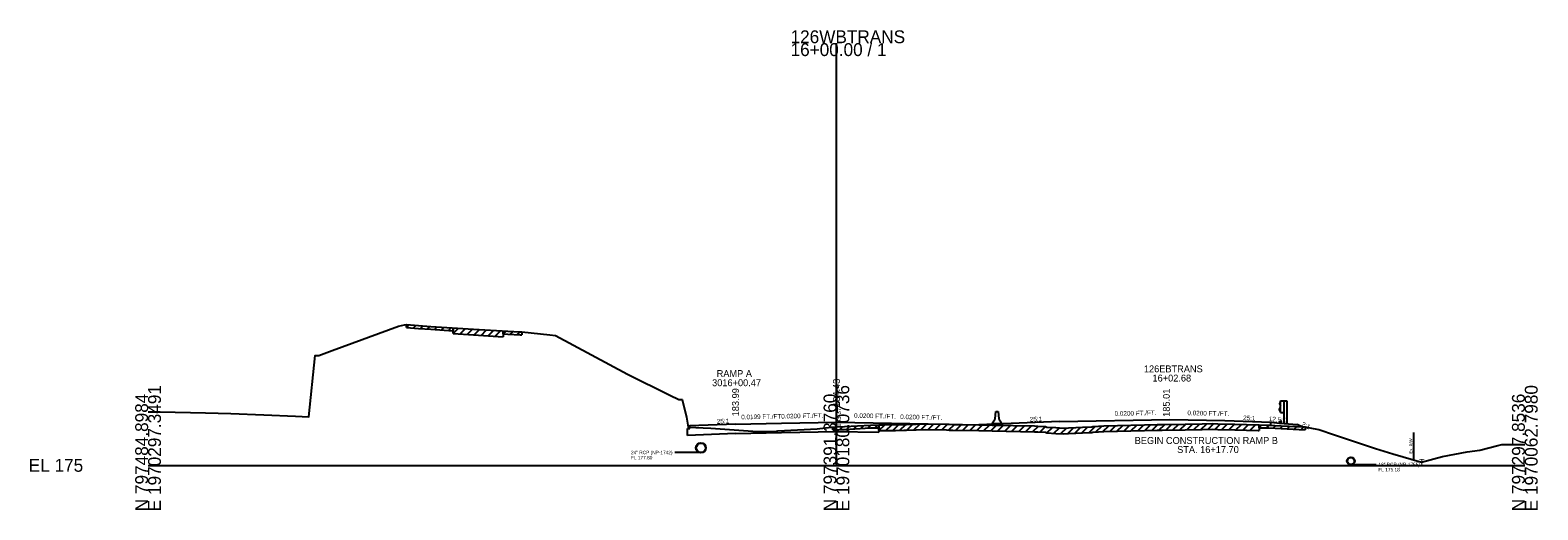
# Model space of a CAD drawing. Extents: x -6494 to 1970605, y -10 to 798140.
# Drawn here: x -25.7 to 302.8, y 8490.3 to 8594.8 of the extents above; entities that cross this region are included whole.
import ezdxf

# ---------------------------------------------------------------- set-up
doc = ezdxf.new("R2010")
doc.units = 0
for name, color, linetype in [('Default', 7, 'Continuous'), ('RD_GPK_XS_Cell', 7, 'Continuous'), ('RD_Sketch1', 7, 'Continuous'), ('RD_XS_Base', 7, 'Continuous'), ('RD_XS_CurbTop', 7, 'Continuous'), ('RD_XS_EarthShd', 7, 'Continuous'), ('RD_XS_ExGround', 7, 'Continuous'), ('RD_XS_ExPaveRet', 7, 'Continuous'), ('RD_XS_ExRW', 7, 'Continuous'), ('RD_XS_GR', 7, 'Continuous'), ('RD_XS_Misc_Line', 7, 'Continuous'), ('RD_XS_Pave', 7, 'Continuous'), ('RD_XS_PaveOvlay', 7, 'Continuous'), ('RD_XS_PaveShd', 7, 'Continuous'), ('RD_XS_Pipe', 7, 'Continuous'), ('RD_XS_TieSlope', 7, 'Continuous'), ('RD_XS_TX_Elev_EX', 7, 'Continuous'), ('RD_XS_TX_Elev_PR', 7, 'Continuous'), ('RD_XS_TX_Notes', 7, 'Continuous'), ('RD_XS_TX_Profile', 7, 'Continuous'), ('RD_XS_TX_ShdSlope', 7, 'Continuous'), ('RD_XS_TX_Slope', 7, 'Continuous'), ('RD_XS_TX_Station', 7, 'Continuous')]:
    doc.layers.add(name, color=color, linetype=linetype)

msp = doc.modelspace()

# ---------------------------------------------------------------- linework, layer by layer
at = {"layer": 'Default'}
for p, q in [((184, 8509.28), (184.58, 8510.11)), ((184, 8509.03), (184, 8509.28)), ((186, 8509.03), (184, 8509.03)), ((184.58, 8510.11), (184.75, 8511.7)), ((184.75, 8511.7), (185.25, 8511.7)), ((185.25, 8511.7), (185.42, 8510.11)), ((185.42, 8510.11), (186, 8509.28)), ((186, 8509.28), (186, 8509.03))]:
    msp.add_line(p, q, dxfattribs=at)
at = {"layer": 'RD_GPK_XS_Cell'}
for p, q in [((150, 8500), (150, 8591.95)), ((0, 8500), (150, 8500)), ((150, 8500), (300, 8500))]:
    msp.add_line(p, q, dxfattribs=at)
at = {"layer": 'RD_XS_Base'}
for p, q in [((244.65, 8508.75), (244.65, 8509.37)), ((117.52, 8508.01), (118.02, 8508.03)), ((117.52, 8506.53), (117.52, 8508.01)), ((128.02, 8506.95), (117.52, 8506.53)), ((118.02, 8508.03), (118.02, 8508.59)), ((128.02, 8506.95), (138, 8507.15)), ((138, 8507.15), (150, 8507.39)), ((150, 8507.39), (159.22, 8507.21))]:
    msp.add_line(p, q, dxfattribs=at)
at = {"layer": 'RD_XS_CurbTop'}
for p, q in [((246.52, 8509.22), (246.77, 8509.67)), ((246.52, 8509.22), (246.99, 8509.18)), ((246.99, 8509.18), (246.93, 8509.62))]:
    msp.add_line(p, q, dxfattribs=at)
msp.add_ellipse((246.84, 8509.59), major_axis=(0, -0.131), ratio=0.686, start_param=1.762783, end_param=4.036677, dxfattribs=at)
at = {"layer": 'RD_XS_EarthShd'}
for p, q in [((244.65, 8509.37), (246.65, 8509.21)), ((118.02, 8508.59), (117.66, 8508.56))]:
    msp.add_line(p, q, dxfattribs=at)
at = {"layer": 'RD_XS_ExGround'}
msp.add_lwpolyline([(0, 8511.65), (2.64, 8511.67), (12.5, 8511.42), (15.24, 8511.38), (18.05, 8511.29), (25.21, 8510.99), (32.13, 8510.72), (35.03, 8510.6), (36.4, 8523.91), (37.18, 8523.94), (40.12, 8525.01), (54.59, 8530.32), (55.9, 8530.57), (56.28, 8530.65), (58.91, 8530.47), (61.63, 8530.26), (70.93, 8529.67), (78.36, 8529.19), (81.05, 8529.09), (81.44, 8529.07), (87.58, 8528.43), (88.8, 8528.3), (104.46, 8519.89), (113.72, 8515.27), (115.64, 8514.32), (116.4, 8514.31), (117.3, 8510.52), (117.7, 8508.34), (122.61, 8508.08), (132.82, 8507.36), (136.91, 8507.46), (137.21, 8507.48), (145.83, 8507.96), (148.86, 8508.29), (149.22, 8508.33), (150, 8508.37), (151.75, 8508.47), (157.44, 8508.77), (162.85, 8508.87), (164.65, 8508.9), (165.29, 8508.91), (169.5, 8509.02), (173.96, 8508.95), (174.6, 8508.94), (175.39, 8508.93), (181, 8508.83), (183.95, 8508.77), (193.13, 8508.58), (193.91, 8508.54), (195.53, 8508.45), (195.82, 8508.32), (197.84, 8508.21), (199.49, 8508.11), (200.58, 8508.18), (202.17, 8508.25), (203.6, 8508.32), (205.65, 8508.38), (205.9, 8508.49), (207.14, 8508.56), (208.3, 8508.61), (217.14, 8508.82), (219.89, 8508.89), (221.01, 8508.91), (225.96, 8508.99), (229.69, 8509.06), (231.99, 8509.1), (233.09, 8509.07), (236.82, 8508.96), (241.9, 8508.83), (244.2, 8508.77), (246.88, 8508.64), (252.11, 8508.36), (253.88, 8508.05), (255.13, 8507.82), (258.54, 8506.64), (267.43, 8503.69), (271.21, 8502.53), (277.51, 8500.66), (282.05, 8501.91), (287.41, 8502.92), (290.22, 8503.32), (294.11, 8504.35), (295.01, 8504.57), (300, 8504.57)], dxfattribs=at)
at = {"layer": 'RD_XS_ExPaveRet'}
for p, q in [((56.28, 8530.02), (56.28, 8530.65)), ((56.28, 8530.02), (58.91, 8529.84)), ((58.91, 8529.84), (61.63, 8529.64)), ((61.63, 8529.64), (66.45, 8529.33)), ((66.45, 8528.7), (66.45, 8529.95)), ((66.45, 8529.95), (66.45, 8529.33)), ((77.4, 8529.25), (77.4, 8528)), ((77.4, 8528.63), (77.4, 8529.25)), ((81.44, 8529.07), (81.44, 8528.44)), ((66.45, 8528.7), (70.93, 8528.42)), ((70.93, 8528.42), (77.4, 8528)), ((77.4, 8528.63), (78.36, 8528.57)), ((78.36, 8528.57), (81.05, 8528.46)), ((81.05, 8528.46), (81.44, 8528.44)), ((149.22, 8507.71), (149.22, 8508.33)), ((149.22, 8507.71), (150, 8507.75)), ((150, 8507.75), (151.75, 8507.84)), ((151.75, 8507.84), (157.44, 8508.15)), ((157.44, 8508.15), (159.22, 8508.18)), ((159.22, 8507.56), (159.22, 8508.81)), ((159.22, 8508.81), (159.22, 8508.18)), ((159.22, 8507.56), (162.85, 8507.62)), ((162.85, 8507.62), (164.65, 8507.65)), ((164.65, 8507.65), (165.29, 8507.66)), ((165.29, 8507.66), (169.5, 8507.77)), ((169.5, 8507.77), (173.96, 8507.7)), ((173.96, 8507.7), (174.6, 8507.69)), ((174.6, 8507.69), (175.39, 8507.68)), ((175.39, 8507.68), (181, 8507.58)), ((181, 8507.58), (183.95, 8507.52)), ((183.95, 8507.52), (193.13, 8507.33)), ((193.13, 8507.33), (193.91, 8507.29)), ((193.91, 8507.29), (195.53, 8507.2)), ((195.53, 8507.2), (195.82, 8507.07)), ((195.82, 8507.07), (197.84, 8506.96)), ((197.84, 8506.96), (199.49, 8506.86)), ((199.49, 8506.86), (200.58, 8506.93)), ((200.58, 8506.93), (202.17, 8507)), ((202.17, 8507), (203.6, 8507.07)), ((203.6, 8507.07), (205.65, 8507.13)), ((205.65, 8507.13), (205.9, 8507.24)), ((205.9, 8507.24), (207.14, 8507.31)), ((207.14, 8507.31), (208.3, 8507.36)), ((208.3, 8507.36), (217.14, 8507.57)), ((217.14, 8507.57), (219.89, 8507.64)), ((219.89, 8507.64), (221.01, 8507.66)), ((221.01, 8507.66), (225.96, 8507.74)), ((225.96, 8507.74), (229.69, 8507.81)), ((229.69, 8507.81), (231.99, 8507.85)), ((231.99, 8507.85), (233.09, 8507.82)), ((233.09, 8507.82), (236.82, 8507.71)), ((236.82, 8507.71), (241.9, 8507.58)), ((241.9, 8507.58), (242.11, 8507.57)), ((242.11, 8508.82), (242.11, 8507.57)), ((242.11, 8508.2), (242.11, 8508.82)), ((242.11, 8508.2), (244.2, 8508.15)), ((244.2, 8508.15), (246.88, 8508.01)), ((246.88, 8508.01), (252.11, 8507.74)), ((252.11, 8508.36), (252.11, 8507.74))]:
    msp.add_line(p, q, dxfattribs=at)
at = {"layer": 'RD_XS_ExRW'}
msp.add_line((275.76, 8507.18), (275.76, 8501.18), dxfattribs=at)
at = {"layer": 'RD_XS_GR'}
for p, q in [((246.79, 8513.92), (246.52, 8513.48)), ((246.52, 8513.48), (246.52, 8513.37)), ((246.52, 8513.37), (246.79, 8512.93)), ((246.52, 8512.22), (246.79, 8512.66)), ((246.79, 8514.08), (247.46, 8514.08)), ((246.79, 8511.51), (246.79, 8514.08)), ((247.46, 8514.08), (248.12, 8514.08)), ((247.46, 8514.08), (247.46, 8509.14)), ((248.12, 8514.08), (248.12, 8509.03)), ((246.52, 8512.11), (246.52, 8512.22)), ((246.79, 8511.67), (246.52, 8512.11)), ((246.79, 8511.51), (247.46, 8511.51))]:
    msp.add_line(p, q, dxfattribs=at)
at = {"layer": 'RD_XS_Misc_Line'}
for p, q in [((56.28, 8530.02), (56.88, 8530.61)), ((57.81, 8529.92), (58.4, 8530.5)), ((59.33, 8529.81), (59.92, 8530.39)), ((60.86, 8529.7), (61.45, 8530.28)), ((62.39, 8529.59), (62.98, 8530.18)), ((63.91, 8529.49), (64.51, 8530.08)), ((65.44, 8529.39), (66.03, 8529.98)), ((66.45, 8528.7), (67.65, 8529.88)), ((67.98, 8528.61), (69.17, 8529.78)), ((69.51, 8528.51), (70.7, 8529.68)), ((71.03, 8528.41), (72.23, 8529.58)), ((72.56, 8528.31), (73.75, 8529.49)), ((74.08, 8528.22), (75.28, 8529.39)), ((75.61, 8528.12), (76.81, 8529.29)), ((77.4, 8528.63), (78, 8529.22)), ((78.92, 8528.55), (79.54, 8529.15)), ((80.45, 8528.49), (81.06, 8529.09)), ((168.38, 8507.74), (169.68, 8509.02)), ((169.91, 8507.76), (171.16, 8509)), ((226.37, 8507.75), (227.67, 8509.02)), ((227.9, 8507.77), (229.19, 8509.05)), ((229.42, 8507.8), (230.72, 8509.07)), ((230.95, 8507.83), (232.23, 8509.09)), ((232.47, 8507.83), (233.71, 8509.05)), ((234, 8507.79), (235.24, 8509.01)), ((149.22, 8507.71), (149.89, 8508.37)), ((150.75, 8507.79), (151.42, 8508.45)), ((152.27, 8507.87), (152.95, 8508.53)), ((153.8, 8507.95), (154.47, 8508.62)), ((155.33, 8508.04), (156, 8508.7)), ((156.85, 8508.12), (157.52, 8508.78)), ((158.38, 8508.17), (159.02, 8508.8)), ((159.22, 8507.56), (160.52, 8508.83)), ((160.75, 8507.58), (162.04, 8508.85)), ((162.28, 8507.61), (163.57, 8508.88)), ((163.8, 8507.63), (165.1, 8508.91)), ((165.33, 8507.66), (166.63, 8508.95)), ((166.85, 8507.7), (168.16, 8508.99)), ((171.43, 8507.74), (172.69, 8508.97)), ((172.96, 8507.72), (174.21, 8508.95)), ((174.48, 8507.7), (175.73, 8508.92)), ((176.01, 8507.67), (177.26, 8508.9)), ((177.54, 8507.64), (178.79, 8508.87)), ((179.06, 8507.61), (180.31, 8508.84)), ((180.59, 8507.59), (181.84, 8508.81)), ((182.12, 8507.56), (183.36, 8508.78)), ((183.64, 8507.53), (184.89, 8508.75)), ((185.17, 8507.5), (186.41, 8508.72)), ((186.69, 8507.46), (187.94, 8508.69)), ((188.22, 8507.43), (189.46, 8508.66)), ((189.75, 8507.4), (190.99, 8508.62)), ((191.27, 8507.37), (192.52, 8508.59)), ((192.8, 8507.34), (194.01, 8508.53)), ((194.32, 8507.26), (195.53, 8508.45)), ((195.85, 8507.07), (197.05, 8508.25)), ((197.38, 8506.98), (198.58, 8508.17)), ((198.9, 8506.9), (200.18, 8508.15)), ((200.43, 8506.92), (201.76, 8508.23)), ((201.95, 8506.99), (203.29, 8508.31)), ((203.48, 8507.06), (204.79, 8508.36)), ((205.01, 8507.11), (206.44, 8508.52)), ((206.53, 8507.27), (207.87, 8508.59)), ((208.06, 8507.35), (209.37, 8508.64)), ((209.58, 8507.39), (210.89, 8508.68)), ((211.11, 8507.43), (212.41, 8508.71)), ((212.64, 8507.47), (213.94, 8508.75)), ((214.16, 8507.5), (215.46, 8508.78)), ((215.69, 8507.54), (216.99, 8508.82)), ((217.21, 8507.58), (218.52, 8508.86)), ((218.74, 8507.61), (220.04, 8508.89)), ((220.27, 8507.65), (221.56, 8508.92)), ((221.79, 8507.67), (223.08, 8508.94)), ((223.32, 8507.7), (224.61, 8508.97)), ((224.84, 8507.72), (226.14, 8508.99)), ((235.53, 8507.75), (236.76, 8508.96)), ((237.05, 8507.7), (238.29, 8508.92)), ((238.58, 8507.66), (239.82, 8508.88)), ((240.1, 8507.62), (241.34, 8508.84)), ((242.11, 8508.2), (242.73, 8508.81)), ((243.64, 8508.16), (244.26, 8508.77)), ((245.17, 8508.1), (245.77, 8508.69)), ((246.69, 8508.02), (247.3, 8508.62)), ((248.22, 8507.94), (248.82, 8508.54)), ((249.74, 8507.86), (250.35, 8508.46)), ((251.27, 8507.78), (251.87, 8508.38))]:
    msp.add_line(p, q, dxfattribs=at)
at = {"layer": 'RD_XS_Pave'}
for p, q in [((128.02, 8508.99), (138, 8509.19)), ((138, 8509.19), (150, 8509.43)), ((150, 8509.43), (174, 8508.95)), ((198.64, 8509.53), (222.64, 8510.01)), ((222.64, 8510.01), (234.64, 8509.77))]:
    msp.add_line(p, q, dxfattribs=at)
at = {"layer": 'RD_XS_PaveOvlay'}
for p, q in [((165.29, 8508.91), (169.5, 8509.02)), ((169.5, 8509.02), (173.96, 8508.95)), ((225.96, 8508.99), (229.69, 8509.06)), ((229.69, 8509.06), (231.99, 8509.1)), ((231.99, 8509.1), (233.09, 8509.07)), ((233.09, 8509.07), (236.82, 8508.96)), ((159.22, 8508.81), (162.85, 8508.87)), ((159.22, 8508.81), (159.22, 8507.21)), ((162.85, 8508.87), (164.65, 8508.9)), ((164.65, 8508.9), (165.29, 8508.91)), ((173.96, 8508.95), (174.6, 8508.94)), ((174.6, 8508.94), (175.39, 8508.93)), ((175.39, 8508.93), (181, 8508.83)), ((181, 8508.83), (183.95, 8508.77)), ((183.95, 8508.77), (193.13, 8508.58)), ((193.13, 8508.58), (193.91, 8508.54)), ((193.91, 8508.54), (195.53, 8508.45)), ((195.53, 8508.45), (195.82, 8508.32)), ((195.82, 8508.32), (197.84, 8508.21)), ((197.84, 8508.21), (199.49, 8508.11)), ((199.49, 8508.11), (200.58, 8508.18)), ((200.58, 8508.18), (202.17, 8508.25)), ((202.17, 8508.25), (203.6, 8508.32)), ((203.6, 8508.32), (205.65, 8508.38)), ((205.65, 8508.38), (205.9, 8508.49)), ((205.9, 8508.49), (207.14, 8508.56)), ((207.14, 8508.56), (208.3, 8508.61)), ((208.3, 8508.61), (217.14, 8508.82)), ((217.14, 8508.82), (219.89, 8508.89)), ((219.89, 8508.89), (221.01, 8508.91)), ((221.01, 8508.91), (225.96, 8508.99)), ((236.82, 8508.96), (241.9, 8508.83)), ((241.9, 8508.83), (242.11, 8508.82)), ((242.11, 8508.82), (244.2, 8508.77)), ((244.2, 8508.77), (244.65, 8508.75))]:
    msp.add_line(p, q, dxfattribs=at)
at = {"layer": 'RD_XS_PaveShd'}
for p, q in [((198.64, 8509.53), (181.05, 8508.82)), ((234.64, 8509.77), (244.65, 8509.37)), ((128.02, 8508.99), (118.02, 8508.59)), ((174, 8508.95), (181.05, 8508.82))]:
    msp.add_line(p, q, dxfattribs=at)
at = {"layer": 'RD_XS_Pipe'}
for p, q in [((119.81, 8502.8), (114.81, 8502.8)), ((262.6, 8500.18), (267.6, 8500.18))]:
    msp.add_line(p, q, dxfattribs=at)
for centre, radius in [((120.47, 8503.8), 1.1), ((120.47, 8503.8), 1), ((262.1, 8500.93), 0.85), ((262.1, 8500.93), 0.75)]:
    msp.add_circle(centre, radius, dxfattribs=at)
at = {"layer": 'RD_XS_TieSlope'}
for p in [(246.65, 8509.21), (251.41, 8508.4)]:
    msp.add_line(p, (250.4, 8508.91), dxfattribs=at)

# ---------------------------------------------------------------- texts
at = {"layer": 'RD_GPK_XS_Cell'}
for s, p in [('126WBTRANS', (140, 8591.95)), ('16+00.00 / 1', (140, 8589.15)), ('EL 175', (-26, 8498.6))]:
    msp.add_text(s, height=2.8, dxfattribs=at).set_placement(p)
for s, p in [('E 1970297.3491', (2.8, 8490)), ('E 1970180.0736', (152.8, 8490)), ('E 1970062.7980', (302.8, 8490)), ('N 797484.8984', (0, 8490)), ('N 797391.3760', (150, 8490)), ('N 797297.8536', (300, 8490))]:
    msp.add_text(s, height=2.8, rotation=90, dxfattribs=at).set_placement(p)
at = {"layer": 'RD_Sketch1'}
msp.add_text('T', height=1.5, dxfattribs=at).set_placement((276.96, 8499.91))
at = {"layer": 'RD_XS_ExRW'}
msp.add_text('Ex. R/W ', height=0.65, rotation=90, dxfattribs=at).set_placement((275.51, 8502.57))
at = {"layer": 'RD_XS_Pipe'}
for s, p in [('24" RCP (NP-1742)', (105.23, 8502.42)), ('FL 177.80', (105.23, 8501.3)), ('18" RCP (NP-1755)', (268.1, 8499.81)), ('FL 175.18', (268.1, 8498.68))]:
    msp.add_text(s, height=0.75, dxfattribs=at).set_placement(p)
at = {"layer": 'RD_XS_TX_Elev_EX'}
msp.add_text('183.37', height=1, rotation=90, dxfattribs=at).set_placement((151, 8508.37))
at = {"layer": 'RD_XS_TX_Elev_PR'}
for s, p in [('183.99', (128.77, 8510.67)), ('184.43', (150.75, 8512.73)), (' 185.01', (222.64, 8510.01))]:
    msp.add_text(s, height=1.5, rotation=90, dxfattribs=at).set_placement(p)
at = {"layer": 'RD_XS_TX_Notes'}
for s, p in [('BEGIN CONSTRUCTION RAMP B', (215, 8504.66)), ('STA. 16+17.70', (224.24, 8502.69))]:
    msp.add_text(s, height=1.5, dxfattribs=at).set_placement(p)
at = {"layer": 'RD_XS_TX_Profile'}
for rotation, p in [(2.2905, (192.15, 8509.52)), (357.7095, (238.6, 8509.86))]:
    msp.add_text('25:1', height=1, rotation=rotation, dxfattribs=at).set_placement(p)
at = {"layer": 'RD_XS_TX_ShdSlope'}
msp.add_text('12.5:1', height=1, rotation=355.4263, dxfattribs=at).set_placement((244.19, 8509.66))
at = {"layer": 'RD_XS_TX_Slope'}
for s, rotation, p in [('25:1', 2.2882, (123.95, 8509.08)), ('0.0199 FT./FT.', 1.1405, (129.26, 8510.01)), ('0.0200 FT./FT.', 1.1458, (137.98, 8510.19)), ('0.0200 FT./FT.', 358.8542, (153.83, 8510.36)), ('0.0200 FT./FT.', 358.8542, (163.89, 8510.08)), ('0.0200 FT./FT.', 1.1469, (210.62, 8510.77)), ('0.0200 FT./FT.', 358.8556, (226.47, 8510.93)), ('2:1', 333.4349, (251.24, 8508.65))]:
    msp.add_text(s, height=1, rotation=rotation, dxfattribs=at).set_placement(p)
at = {"layer": 'RD_XS_TX_Station'}
for s, p in [('RAMP A', (123.9, 8519.24)), ('126EBTRANS', (217, 8520.26)), ('16+02.68', (218.87, 8518.26)), ('3016+00.47', (122.91, 8517.24))]:
    msp.add_text(s, height=1.5, dxfattribs=at).set_placement(p)

doc.saveas('drawing.dxf')
